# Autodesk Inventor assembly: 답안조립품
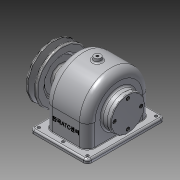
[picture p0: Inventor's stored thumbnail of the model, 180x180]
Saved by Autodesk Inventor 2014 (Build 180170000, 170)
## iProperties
Created: 2015-09
Part Number: 답안조립품
Document SubType Name: Assembly
Designer: Administrator
Author: Administrator
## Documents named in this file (12)
- C:\Users\Administrator\Desktop\450907V1045\답안조립품.iam
- C:\Users\Administrator\Desktop\450907V1045\1-본체.ipt
- C:\Users\Administrator\Desktop\450907V1045\뒤커버.ipt
- C:\Users\Administrator\Desktop\450907V1045\볼트 M3 x 8.ipt
- C:\Users\Administrator\Desktop\450907V1045\베어링 6203.ipt
- C:\Users\Administrator\Desktop\450907V1045\축.ipt
- C:\Users\Administrator\Desktop\450907V1045\스퍼기어.ipt
- C:\Users\Administrator\Desktop\450907V1045\키 - 6 x 6 x 22.ipt
- C:\Users\Administrator\Desktop\450907V1045\앞커버.ipt
- C:\Users\Administrator\Desktop\450907V1045\오일 실 17 32 8.ipt
- C:\Users\Administrator\Desktop\450907V1045\키 - 5 x 5 x 18.ipt
- C:\Users\Administrator\Desktop\450907V1045\V-벨트풀리.ipt
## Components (6 placed, 3 different names)
1. 1-본체:1
2. V-벨트풀리:1
3. ISO 4762 M3 x 8:1
4. ISO 4762 M3 x 8:2
5. ISO 4762 M3 x 8:3
6. ISO 4762 M3 x 8:4
